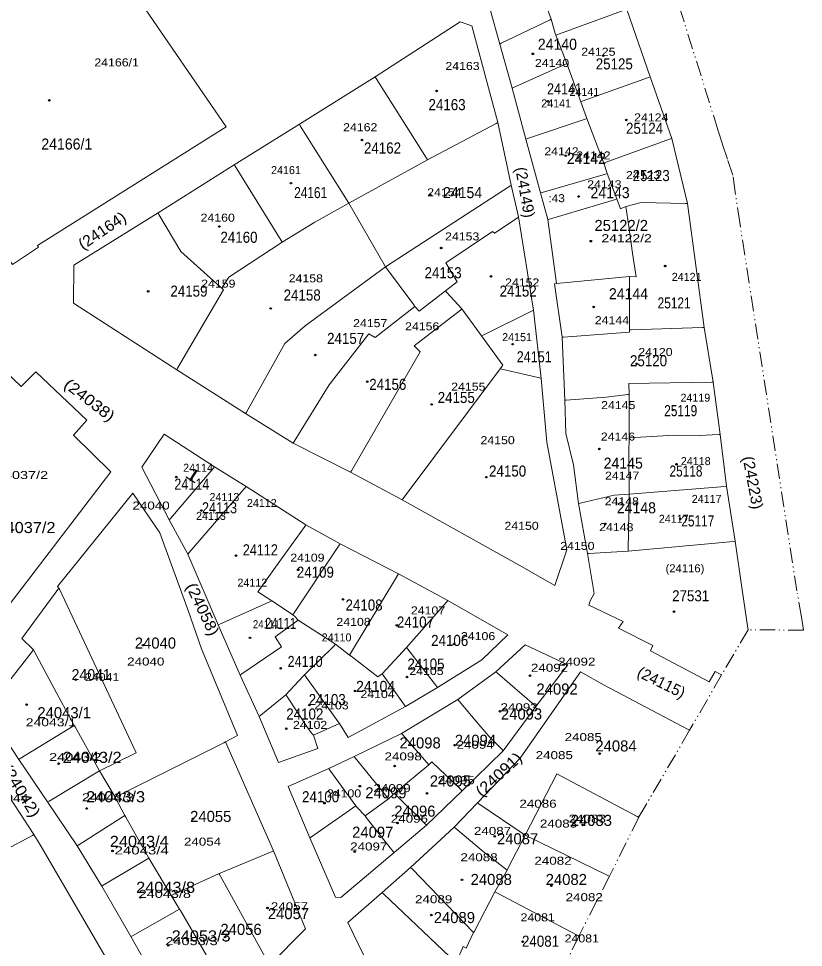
# Model space of a CAD drawing. Extents: x 649608 to 651081, y 237980 to 241202.
# Drawn here: x 650826.5 to 651081.3, y 238358.7 to 238660.5 of the extents above; entities that cross this region are included whole.
import ezdxf
from ezdxf.enums import TextEntityAlignment as Align

# ---------------------------------------------------------------- set-up
doc = ezdxf.new("R2010")
doc.units = 0
doc.header["$PDMODE"] = 32
doc.header["$PDSIZE"] = 0.5
doc.linetypes.add('DASH_DOUBLE_DOT', pattern=[9.2, 5, -1.2, 0.3, -1.2, 0.3, -1.2])
for name, color, linetype in [('19', 7, 'Continuous'), ('20', 7, 'Continuous'), ('6', 7, 'Continuous')]:
    doc.layers.add(name, color=color, linetype=linetype)
for name, color, linetype, lineweight in [('2', 7, 'DASH_DOUBLE_DOT', 13), ('3', 7, 'Continuous', 13), ('5', 7, 'Continuous', 13), ('52', 7, 'DASH_DOUBLE_DOT', 13)]:
    doc.layers.add(name, color=color, linetype=linetype, lineweight=lineweight)

msp = doc.modelspace()

# ---------------------------------------------------------------- linework, layer by layer
at = {"layer": '2'}
msp.add_line((651063.379, 238461.895), (651054.781, 238447.238), dxfattribs=at)
msp.add_lwpolyline([(651044.396, 238429.284), (651027.852, 238400.968), (651018.368, 238381.839), (651008.402, 238362.401), (650999.718, 238344.376)], dxfattribs=at)
at = {"layer": '3'}
msp.add_line((650893.931, 238625.308), (650851.505, 238687.244), dxfattribs=at)
for points in [[(650948.594, 238756.104), (650948.647, 238755.953), (650951.021, 238749.525), (650955.792, 238735.14), (650959.886, 238723.149), (650963.669, 238711.97), (650969.049, 238695.287), (650974.422, 238679.159), (650979.638, 238663.433), (650982.757, 238652.196), (650986.731, 238637.816), (650991.239, 238621.324), (650995.965, 238603.801), (650998.364, 238595.203), (651001.152, 238574.45)], [(651063.379, 238461.895), (651063.305, 238462.395), (651061.473, 238474.842), (651059.17, 238490.663), (651056.406, 238508.519), (651054.341, 238525.331), (651052.076, 238542.318), (651049.059, 238560.151), (651043.67, 238600.336), (651038.659, 238621.53), (651031.567, 238641.552), (651023.953, 238663.427), (651012.132, 238696.964), (651006.434, 238713.032), (651000.56, 238729.25)], [(650851.505, 238687.244), (650818.255, 238663.558), (650782.391, 238637.529), (650824.601, 238580.584), (650833.018, 238586.179), (650832.688, 238586.745), (650893.931, 238625.308)], [(650973.727, 238658.121), (650969.91, 238659.349), (650942.264, 238641.535), (650917.692, 238626.144), (650896.579, 238612.976), (650871.831, 238597.331)], [(650973.727, 238658.121), (650982.081, 238626.658), (650986.506, 238606.381), (650988.849, 238596.017), (650993.721, 238565.756), (650996.2, 238543.588)], [(650871.831, 238597.331), (650844.537, 238580.328), (650844.399, 238568.022), (650877.886, 238546.351), (650900.226, 238532.148), (650915.657, 238522.524), (650934.332, 238513.079), (650951.062, 238504.071)], [(651001.152, 238574.45), (651000.495, 238574.326), (651002.965, 238556.914), (651003.844, 238536.477)], [(650856.496, 238513.231), (650844.324, 238525.087), (650848.714, 238529.96), (650832.101, 238545.72), (650827.429, 238540.969), (650809.783, 238557.7), (650779.446, 238551.594)], [(650996.2, 238543.588), (650998.024, 238522.875), (651002.389, 238499.63)], [(651003.844, 238536.477), (651004.245, 238525.696), (651006.676, 238515.537), (651008.325, 238502.903), (651011.189, 238486.675)], [(650866.546, 238514.77), (650873.836, 238525.457), (650890.127, 238514.848), (650900.429, 238508.467)], [(650856.496, 238513.231), (650783.062, 238417.168), (650770.127, 238405.165)], [(650866.546, 238514.77), (650875.391, 238497.58), (650881.454, 238486.467), (650891.353, 238463.51), (650898.529, 238447.22), (650904.638, 238433.734)], [(650962.59, 238443.143), (650976.951, 238452.166), (650985.353, 238460.261), (650965.945, 238471.388), (650949.856, 238480.088), (650930.982, 238489.851), (650919.848, 238495.996), (650900.429, 238508.467)], [(650839.656, 238475.401), (650839.146, 238475.982), (650863.655, 238506.27)], [(650893.73, 238425.465), (650897.595, 238427.607), (650885.968, 238455.715), (650881.57, 238468.139), (650872.443, 238493.367), (650863.655, 238506.27)], [(650951.062, 238504.071), (650989.055, 238482.851), (651000.618, 238476.318)], [(651000.618, 238476.318), (651004.549, 238487.858), (651002.389, 238499.63)], [(651011.189, 238486.675), (651013.346, 238473.653), (651012.121, 238471.268), (651011.66, 238469.957), (651022.804, 238464.57), (651021.346, 238462.448), (651032.415, 238456.837), (651031.735, 238455.063), (651050.691, 238444.969), (651052.652, 238448.365), (651054.281, 238447.503), (651054.781, 238447.238)], [(650831.358, 238455.416), (650827.556, 238459.105), (650839.656, 238475.401)], [(651004.89, 238450.516), (650990.971, 238456.999), (650981.52, 238448.274), (650969.179, 238439.249), (650950.825, 238428.235), (650935.445, 238420.778), (650927.23, 238416.848)], [(650826.605, 238419.813), (650815.978, 238435.816), (650831.358, 238455.416)], [(650921.125, 238394.337), (650929.421, 238375.092), (650931.134, 238374.964), (650948.472, 238389.538), (650958.921, 238398.464), (650970.499, 238409.636), (650983.871, 238422.598), (650994.485, 238437.002), (651004.89, 238450.516)], [(651008.989, 238448.245), (650989.363, 238420.245), (650975.477, 238405.743), (650967.944, 238397.799), (650953.805, 238384.736), (650944.611, 238376.541)], [(651044.396, 238429.284), (651043.896, 238429.548), (651016.601, 238443.963), (651008.989, 238448.245)], [(650930.686, 238431.461), (650933.591, 238426.914), (650952.172, 238436.968), (650962.59, 238443.143)], [(650806.229, 238431.585), (650811.125, 238425.42), (650822.189, 238409.657), (650831.543, 238395.385)], [(650904.638, 238433.734), (650910.948, 238418.783), (650923.741, 238423.365), (650922.292, 238427.632), (650930.686, 238431.461)], [(650919.66, 238364.802), (650909.331, 238390.132), (650893.73, 238425.465)], [(650896.629, 238341.525), (650885.025, 238330.555), (650880.347, 238330.711), (650871.33, 238347.558), (650863.025, 238362.258), (650853.548, 238378.601), (650845.597, 238391.685), (650835.988, 238405.983), (650826.605, 238419.813)], [(650927.23, 238416.848), (650914.026, 238411.03), (650921.125, 238394.337)], [(650831.543, 238395.385), (650833.862, 238391.545), (650864.894, 238338.148)], [(650944.611, 238376.541), (650933.47, 238366.808), (650953.787, 238324.857)], [(650919.66, 238364.802), (650908.054, 238352.949), (650896.629, 238341.525)]]:
    msp.add_lwpolyline(points, dxfattribs=at)
at = {"layer": '5'}
for p, q in [((650933.706, 238600.448), (650945.648, 238579.76)), ((651001.152, 238574.45), (651024.878, 238576.658)), ((651024.886, 238558.55), (651024.886, 238559.381)), ((651001.259, 238415.17), (650990.949, 238395.151))]:
    msp.add_line(p, q, dxfattribs=at)
for points in [[(650968.909, 238740.542), (650970.097, 238737.227), (650970.888, 238737.388), (650974.373, 238727.694), (650977.245, 238720.162), (650978.452, 238717.453), (650983.561, 238704.298), (650984.021, 238702.059), (650989.061, 238688.248), (650989.987, 238685.484), (650995.652, 238670.697), (650999.401, 238660.225)], [(651000.938, 238655.114), (651023.453, 238663.246), (651023.953, 238663.427)], [(650982.757, 238652.196), (650983.257, 238652.437), (650998.901, 238659.984), (650999.401, 238660.225)], [(650999.401, 238660.225), (651000.788, 238655.614), (651000.938, 238655.114)], [(651023.679, 238599.446), (651023.179, 238599.223), (651021.948, 238598.674), (651020.779, 238601.853), (651017.617, 238610.113), (651016.522, 238613.491), (651010.995, 238627.983), (651009.029, 238633.439), (651004.574, 238645.828), (651000.938, 238655.114)], [(650986.731, 238637.816), (650987.231, 238638.041), (651004.074, 238645.603), (651004.574, 238645.828)], [(650942.264, 238641.535), (650942.579, 238641.035), (650958.934, 238615.066), (650959.249, 238614.566)], [(651009.029, 238633.439), (651009.529, 238633.619), (651031.067, 238641.372), (651031.567, 238641.552)], [(650991.239, 238621.324), (650991.739, 238621.493), (651010.495, 238627.814), (651010.995, 238627.983)], [(650917.692, 238626.144), (650918.004, 238625.644), (650933.706, 238600.448)], [(650959.249, 238614.566), (650981.581, 238626.393), (650982.081, 238626.658)], [(651016.522, 238613.491), (651017.022, 238613.673), (651038.159, 238621.348), (651038.659, 238621.53)], [(650896.579, 238612.976), (650896.888, 238612.476), (650911.797, 238588.341), (650912.106, 238587.841)], [(650912.106, 238587.841), (650922.738, 238594.306), (650933.706, 238600.448), (650959.249, 238614.566)], [(650995.965, 238603.801), (650996.465, 238603.947), (651017.117, 238609.967), (651017.617, 238610.113)], [(650945.648, 238579.76), (650986.006, 238606.055), (650986.506, 238606.381)], [(650998.364, 238595.203), (650998.864, 238595.351), (651020.279, 238601.705), (651020.779, 238601.853)], [(651023.679, 238599.446), (651028.666, 238600.738), (651043.17, 238600.349), (651043.67, 238600.336)], [(650871.831, 238597.331), (650872.126, 238596.831), (650879.229, 238584.806), (650892.001, 238573.313), (650892.501, 238572.863)], [(651024.878, 238576.658), (651027.082, 238576.554), (651025.822, 238584.235), (651024.665, 238592.892), (651023.679, 238599.446)], [(650965.157, 238572.008), (650968.88, 238574.93), (650965.282, 238581.116), (650980.445, 238591.321), (650981.091, 238590.724), (650988.349, 238595.676), (650988.849, 238596.017)], [(650892.501, 238572.863), (650894.81, 238576.474), (650912.106, 238587.841)], [(650900.226, 238532.148), (650900.505, 238532.648), (650912.946, 238554.957), (650919.549, 238560.665), (650945.648, 238579.76)], [(650945.648, 238579.76), (650954.852, 238567.439), (650955.225, 238566.939)], [(651024.886, 238559.381), (651024.878, 238576.158), (651024.878, 238576.658)], [(650877.886, 238546.351), (650878.178, 238546.851), (650893.069, 238572.341), (650892.501, 238572.863)], [(650955.225, 238566.939), (650956.571, 238565.417), (650965.157, 238572.008)], [(650965.157, 238572.008), (650965.61, 238571.508), (650970.464, 238566.146), (650976.876, 238557.423)], [(650915.657, 238522.524), (650915.965, 238523.024), (650927.359, 238541.515), (650940.277, 238558.074), (650942.335, 238556.889), (650955.225, 238566.939)], [(650934.332, 238513.079), (650934.621, 238513.579), (650956.929, 238552.178), (650955.015, 238554.121), (650969.964, 238565.757), (650970.464, 238566.146)], [(650976.876, 238557.423), (650977.376, 238557.67), (650993.221, 238565.509), (650993.721, 238565.756)], [(651002.965, 238556.914), (651003.465, 238556.951), (651024.886, 238558.55)], [(651024.886, 238559.381), (651025.386, 238559.397), (651048.559, 238560.135), (651049.059, 238560.151)], [(650976.876, 238557.423), (650983.783, 238547.847), (650982.877, 238546.65), (650951.062, 238504.071)], [(650982.877, 238546.65), (650983.377, 238546.535), (650995.7, 238543.703), (650996.2, 238543.588)], [(651024.789, 238538.39), (651024.647, 238541.967), (651051.576, 238542.312), (651052.076, 238542.318)], [(651024.789, 238538.39), (651024.289, 238538.33), (651017.348, 238537.503), (651004.344, 238536.515), (651003.844, 238536.477)], [(651024.756, 238524.309), (651024.757, 238524.809), (651024.766, 238528.536), (651024.789, 238538.39)], [(651024.756, 238524.309), (651039.462, 238525.108), (651047.477, 238525.043), (651053.841, 238525.31), (651054.341, 238525.331)], [(651024.814, 238506), (651024.695, 238519.506), (651024.756, 238524.309)], [(650890.127, 238514.848), (650889.7, 238514.348), (650875.818, 238498.08), (650875.391, 238497.58)], [(650881.454, 238486.467), (650881.885, 238486.967), (650900.429, 238508.467)], [(651024.814, 238506), (651055.906, 238508.479), (651056.406, 238508.519)], [(651008.325, 238502.903), (651008.825, 238503.02), (651019.904, 238505.608), (651024.814, 238506)], [(651024.424, 238487.408), (651024.434, 238487.908), (651024.814, 238506)], [(650908.779, 238471.344), (650904.183, 238474.277), (650912.438, 238485.704), (650919.488, 238495.496), (650919.848, 238495.996)], [(650915.57, 238466.768), (650930.648, 238489.351), (650930.982, 238489.851)], [(651024.424, 238487.408), (651058.67, 238490.616), (651059.17, 238490.663)], [(651011.189, 238486.675), (651011.689, 238486.703), (651024.424, 238487.408)], [(650949.856, 238480.088), (650949.555, 238479.588), (650933.977, 238453.698), (650929.459, 238457.186), (650917.357, 238465.075)], [(650839.656, 238475.401), (650839.89, 238474.901), (650864.731, 238421.934), (650852.856, 238416.039), (650857.901, 238407.552)], [(650891.353, 238463.51), (650891.853, 238463.735), (650908.779, 238471.344)], [(650908.779, 238471.344), (650909.279, 238471.007), (650915.57, 238466.768)], [(650952.492, 238456.128), (650965.504, 238470.888), (650965.945, 238471.388)], [(650898.529, 238447.22), (650899.029, 238447.563), (650911.919, 238456.396), (650909.855, 238459.655), (650916.857, 238464.714), (650917.357, 238465.075)], [(650917.357, 238465.075), (650916.07, 238466.294), (650915.57, 238466.768)], [(650919.315, 238447.25), (650928.959, 238456.696), (650929.459, 238457.186)], [(650933.977, 238453.698), (650934.477, 238453.314), (650943.193, 238446.621), (650944.524, 238447.654), (650952.492, 238456.128)], [(650952.492, 238456.128), (650952.881, 238455.628), (650962.201, 238443.643), (650962.59, 238443.143)], [(650831.358, 238455.416), (650831.625, 238454.916), (650838.973, 238441.17), (650844.628, 238430.84)], [(650913.319, 238440.794), (650918.851, 238446.75), (650919.315, 238447.25)], [(650930.686, 238431.461), (650930.326, 238431.961), (650919.315, 238447.25)], [(650952.172, 238436.968), (650951.814, 238437.468), (650944.882, 238447.154), (650944.524, 238447.654)], [(650994.485, 238437.002), (650993.985, 238437.437), (650982.02, 238447.839), (650981.52, 238448.274)], [(650904.638, 238433.734), (650905.138, 238434.141), (650913.319, 238440.794)], [(650913.319, 238440.794), (650913.648, 238440.294), (650920.507, 238429.856), (650921.891, 238428.132), (650922.292, 238427.632)], [(650983.871, 238422.598), (650983.382, 238423.098), (650979.202, 238427.374), (650975.3, 238431.947), (650969.598, 238438.749), (650969.179, 238439.249)], [(650844.628, 238430.84), (650827.105, 238420.119), (650826.605, 238419.813)], [(650844.628, 238430.84), (650844.906, 238430.34), (650852.856, 238416.039)], [(650857.901, 238407.552), (650893.23, 238425.215), (650893.73, 238425.465)], [(650959.727, 238418.028), (650951.261, 238427.735), (650950.825, 238428.235)], [(650935.445, 238420.778), (650935.85, 238420.278), (650946.59, 238407.034), (650939.036, 238401.438)], [(650936.026, 238404.697), (650927.592, 238416.348), (650927.23, 238416.848)], [(650948.562, 238408.724), (650949.062, 238409.141), (650959.727, 238418.028)], [(650959.727, 238418.028), (650960.21, 238418.528), (650960.726, 238419.062), (650969.999, 238410.118), (650970.499, 238409.636)], [(650835.988, 238405.983), (650836.488, 238406.281), (650852.856, 238416.039)], [(651001.259, 238415.17), (651027.352, 238401.235), (651027.852, 238400.968)], [(650857.901, 238407.552), (650858.163, 238407.052), (650861.034, 238401.566)], [(650948.562, 238408.724), (650947.09, 238407.462), (650946.59, 238407.034)], [(650958.921, 238398.464), (650958.421, 238398.959), (650948.562, 238408.724)], [(650921.125, 238394.337), (650921.625, 238394.685), (650936.026, 238404.697)], [(650939.036, 238401.438), (650936.488, 238404.197), (650936.026, 238404.697)], [(650990.949, 238395.151), (650975.977, 238405.401), (650975.477, 238405.743)], [(650861.034, 238401.566), (650846.097, 238392.005), (650845.597, 238391.685)], [(650861.034, 238401.566), (650861.316, 238401.066), (650868.88, 238387.673)], [(650939.036, 238401.438), (650939.432, 238400.938), (650948.076, 238390.038), (650948.472, 238389.538)], [(650831.543, 238395.385), (650831.043, 238395.117), (650822.125, 238390.345), (650814.267, 238385.733), (650807.944, 238381.701)], [(650967.944, 238397.799), (650968.444, 238397.378), (650977.388, 238389.838), (650985.122, 238383.847), (650981.123, 238376.78)], [(650985.122, 238383.847), (650985.38, 238384.347), (650990.949, 238395.151)], [(650990.949, 238395.151), (651017.868, 238382.082), (651018.368, 238381.839)], [(650891.47, 238382.627), (650908.831, 238389.922), (650909.331, 238390.132)], [(650868.88, 238387.673), (650854.048, 238378.897), (650853.548, 238378.601)], [(650868.88, 238387.673), (650869.177, 238387.173), (650876.065, 238375.574), (650878.792, 238371.179)], [(650974.241, 238363.562), (650954.288, 238384.236), (650953.805, 238384.736)], [(650876.065, 238375.574), (650876.565, 238375.803), (650891.47, 238382.627)], [(650891.47, 238382.627), (650891.65, 238382.678), (650907.778, 238353.449), (650908.054, 238352.949)], [(650944.611, 238376.541), (650945.111, 238376.065), (650968.571, 238353.722), (650962.028, 238341.864)], [(650981.123, 238376.78), (650974.501, 238364.062), (650974.241, 238363.562)], [(650981.123, 238376.78), (650981.623, 238376.516), (651007.902, 238362.665), (651008.402, 238362.401)], [(650878.792, 238371.179), (650863.525, 238362.541), (650863.025, 238362.258)], [(650878.792, 238371.179), (650879.082, 238370.679), (650887.429, 238356.276)], [(650968.571, 238353.722), (650968.793, 238354.222), (650970.908, 238358.996), (650971.828, 238358.515), (650974.241, 238363.562)]]:
    msp.add_lwpolyline(points, dxfattribs=at)
at = {"layer": '52'}
for p, q in [((651081.326, 238461.798), (651063.379, 238461.895)), ((651054.781, 238447.238), (651044.396, 238429.284))]:
    msp.add_line(p, q, dxfattribs=at)
msp.add_lwpolyline([(651081.326, 238461.798), (651080.759, 238465.959), (651079.219, 238474.548), (651060.64, 238594.17), (651059.155, 238604.083), (651058.44, 238609.613), (651056.636, 238614.788), (651055.058, 238619.632), (651053.581, 238624.323), (651040.863, 238664.96), (651038.983, 238669.983), (651037.177, 238674.674), (651035.497, 238679.416), (651026.689, 238704.697), (651005.715, 238762.299), (651000.638, 238776.753), (650995.266, 238791.57), (650978.475, 238836.494), (650965.122, 238871.866), (650947.956, 238918.149), (650946.31, 238922.796), (650942.749, 238932.427)], dxfattribs=at)
at = {"layer": '6'}
for p in [(650993.479, 238649.02), (651016.363, 238648.433), (650962.247, 238636.957), (650836.553, 238633.914), (650998.435, 238633.576), (651023.854, 238627.521), (650938.053, 238620.991), (651004.155, 238615.892), (651029.491, 238610.102), (650914.952, 238606.992), (650960.17, 238603.209), (651008.377, 238602.658), (650891.703, 238592.919), (651012.305, 238588.151), (650963.73, 238585.899), (651036.448, 238580.059), (650979.897, 238576.72), (650868.609, 238571.841), (650908.393, 238566.298), (651013.224, 238566.786), (650986.91, 238554.672), (650922.844, 238551.142), (651027.198, 238548.314), (650939.761, 238542.543), (650960.658, 238535.108), (651039.027, 238533.313), (651015.081, 238520.646), (651040.129, 238515.665), (650877.752, 238511.518), (650978.382, 238511.484), (650885.855, 238500.657), (651041.343, 238497.963), (651017.047, 238496.337), (650897.152, 238485.988), (650917.322, 238481.382), (650931.883, 238471.774), (651039.298, 238467.816), (650949.325, 238463.354), (650901.653, 238459.282), (650866.936, 238456.911), (650967.869, 238457.265), (650911.615, 238449.404), (650952.629, 238446.548), (650992.584, 238447), (650845.058, 238445.72), (650935.797, 238442.05), (650829.154, 238437.614), (650920.951, 238437.441), (650982.853, 238435.436), (650913.432, 238429.788), (650968.101, 238424.442), (651015.173, 238421.698), (650839.547, 238418.411), (650948.624, 238417.634), (650937.336, 238411.108), (650959.102, 238408.763), (650925.858, 238405.592), (650848.623, 238403.862), (650883.185, 238400.519), (650949.556, 238399.131), (651009.653, 238398.504), (650981.137, 238394.795), (650857.045, 238390.083), (650935.654, 238389.83), (650970.525, 238380.68), (650999.525, 238378.776), (650866.05, 238374.965), (650907.354, 238371.54), (650960.53, 238369.229), (650893.529, 238362.101), (650875.147, 238359.368), (650990.169, 238360.578)]:
    msp.add_point(p, dxfattribs=at)

# ---------------------------------------------------------------- texts
at = {"layer": '19'}
for s, width, p in [('24140', 0.95, (650995.1, 238650.326)), ('25125', 0.9, (651013.909, 238643.927)), ('24141', 0.85, (650998.093, 238635.822)), ('24163', 0.9, (650959.616, 238630.703)), ('25124', 0.9, (651023.741, 238623.023)), ('24166/1', 0.95, (650833.928, 238617.904)), ('24162', 0.9, (650938.668, 238616.625)), ('24142', 0.95, (651004.505, 238613.211)), ('25123', 0.9, (651025.88, 238607.665)), ('24161', 0.8, (650916.01, 238602.121)), ('24154', 0.95, (650964.318, 238602.121)), ('24143', 0.95, (651012.201, 238602.119)), ('24160', 0.9, (650892.068, 238587.616)), ('24153', 0.9, (650958.333, 238576.097)), ('24159', 0.9, (650875.824, 238570.125)), ('24152', 0.9, (650982.701, 238570.125)), ('24158', 0.9, (650912.589, 238568.845)), ('24144', 0.95, (651018.186, 238569.27)), ('25121', 0.8, (651034.002, 238566.284)), ('24157', 0.9, (650926.698, 238554.767)), ('24151', 0.85, (650988.258, 238548.794)), ('25120', 0.9, (651025.024, 238547.513)), ('24156', 0.9, (650940.378, 238539.835)), ('24155', 0.9, (650962.608, 238535.569)), ('25119', 0.8, (651036.14, 238531.302)), ('24145', 0.95, (651016.476, 238514.238)), ('24150', 0.9, (650979.281, 238511.679)), ('25118', 0.8, (651037.849, 238511.678)), ('24114', 0.85, (650877.105, 238507.413)), ('24113', 0.85, (650886.083, 238499.734)), ('24148', 0.95, (651020.749, 238499.733)), ('25117', 0.8, (651041.698, 238495.467)), ('24037/2', 1.1, (650819.392, 238493.334)), ('24112', 0.85, (650899.336, 238486.082)), ('24109', 0.9, (650916.863, 238478.829)), ('27531', 0.9, (651038.705, 238471.15)), ('24108', 0.9, (650932.681, 238468.164)), ('24111', 0.75, (650906.603, 238462.191)), ('24107', 0.9, (650949.354, 238462.618)), ('24106', 0.9, (650960.469, 238456.645)), ('24110', 0.85, (650913.87, 238449.819)), ('24105', 0.9, (650952.774, 238448.966)), ('24041', 0.95, (650843.76, 238445.553)), ('24104', 0.95, (650936.101, 238441.714)), ('24103', 0.9, (650920.711, 238437.448)), ('24102', 0.9, (650913.443, 238432.755)), ('24043/2', 1.1, (650840.859, 238418.686)), ('24043/3', 1.1, (650848.463, 238405.879)), ('24100', 0.9, (650918.574, 238405.879)), ('24043/4', 1.1, (650856.158, 238391.374)), ('24043/8', 1.1, (650864.708, 238376.443)), ('24053/3', 1.1, (650876.25, 238360.658)), ('24081', 0.9, (650989.968, 238358.952))]:
    msp.add_text(s, height=3.6, dxfattribs=dict(at, width=width)).set_placement(p)
for s, rotation, p in [('(24149)', 280.326, (650987.744, 238611.879)), ('(24115)', 333.478, (651027.001, 238446.946))]:
    msp.add_text(s, height=3.6, rotation=rotation, dxfattribs=at).set_placement(p)
for s, rotation, width, p in [('(24164)', 34.23, 1.05, (650847.463, 238585.208)), ('(24038)', 322.507, 1.15, (650840.912, 238540.938)), ('(24223)', 280.748, 1.05, (651061.55, 238517.936)), ('(24058)', 295.392, 1.1, (650880.766, 238476.074)), ('(24091)', 42.65, 1.1, (650976.91, 238407.43)), ('(24042)', 301.484, 1.15, (650820.818, 238416.872))]:
    msp.add_text(s, height=3.6, rotation=rotation, dxfattribs=dict(at, width=width)).set_placement(p)
for s, p in [('25122/2', (651013.482, 238591.454)), ('24040', (650864.28, 238455.792)), ('24092', (650994.67, 238440.861)), ('24043/1', (650832.645, 238433.182)), ('24093', (650983.127, 238432.756)), ('24098', (650950.209, 238423.37)), ('24094', (650968.164, 238424.223)), ('24084', (651013.792, 238422.378)), ('24095', (650960.042, 238410.999)), ('24099', (650939.095, 238407.159)), ('24096', (650948.5, 238401.187)), ('24055', (650882.235, 238399.479)), ('24083', (651005.786, 238398.2)), ('24097', (650934.819, 238394.361)), ('24087', (650981.846, 238392.227)), ('24088', (650973.296, 238379.002)), ('24082', (650997.664, 238379.002)), ('24057', (650907.458, 238367.91)), ('24089', (650961.326, 238366.63)), ('24056', (650892.068, 238362.791))]:
    msp.add_text(s, height=3.6, dxfattribs=at).set_placement(p)
at = {"layer": '20'}
for s, width, p in [('24125', 1.15, (651009.201, 238648.383)), ('24166/1', 1.15, (650851.144, 238644.919)), ('24163', 1.15, (650965.096, 238643.759)), ('24140', 1.15, (650994.163, 238644.738)), ('24124', 1.15, (651026.375, 238627.057)), ('24162', 1.15, (650931.908, 238623.87)), ('24142', 1.15, (650997.214, 238616.043)), ('24142', 1.15, (651007.601, 238614.697)), ('24123', 1.15, (651023.719, 238608.316)), ('24143', 1.15, (651011.149, 238605.333)), ('24154', 1.15, (650959.204, 238602.723)), (':43', 1.1, (650998.551, 238600.816)), ('24160', 1.15, (650885.628, 238594.495)), ('24153', 1.15, (650964.995, 238588.394)), ('24122/2', 1.3, (651015.767, 238587.808)), ('24158', 1.15, (650914.234, 238574.777)), ('24159', 1.15, (650885.836, 238573.059)), ('24152', 1.15, (650984.485, 238573.441)), ('24157', 1.15, (650935.144, 238560.218)), ('24156', 1.15, (650952.011, 238559.187)), ('24144', 1.15, (651013.616, 238561.186)), ('24120', 1.15, (651027.737, 238550.854)), ('24155', 1.15, (650966.989, 238539.584)), ('24145', 1.15, (651015.655, 238533.585)), ('24146', 1.15, (651015.575, 238523.375)), ('24150', 1.15, (650976.495, 238522.2)), ('24037/2', 1.35, (650819.179, 238510.887)), ('24147', 1.15, (651016.921, 238510.689)), ('24148', 1.15, (651016.816, 238502.352)), ('24040', 1.25, (650863.507, 238500.967)), ('24150', 1.15, (650984.267, 238494.383)), ('24148', 1.15, (651015.03, 238493.95)), ('24150', 1.15, (651002.388, 238487.862)), ('24109', 1.15, (650914.745, 238484.048)), ('(24116)', 1.05, (651036.576, 238480.578)), ('24107', 1.15, (650953.899, 238466.912)), ('24111', 0.9, (650902.609, 238462.428)), ('24108', 1.15, (650929.72, 238463.176)), ('24106', 1.15, (650970.158, 238458.554)), ('24040', 1.25, (650861.792, 238450.294)), ('24092', 1.25, (651001.717, 238450.268)), ('24105', 1.15, (650953.397, 238447.22)), ('24092', 1.25, (650992.866, 238448.274)), ('24041', 1.15, (650848.137, 238445.238)), ('24104', 1.15, (650937.512, 238439.718)), ('24103', 1.15, (650922.573, 238436.045)), ('24093', 1.25, (650982.998, 238435.445)), ('24043/1', 1.3, (650828.884, 238430.563)), ('24102', 1.15, (650915.623, 238429.714)), ('24085', 1.25, (651003.808, 238425.763)), ('24094', 1.25, (650968.741, 238423.26)), ('24085', 1.25, (650994.41, 238419.89)), ('24043/2', 1.35, (650836.455, 238419.277)), ('24098', 1.25, (650945.344, 238419.482)), ('24095', 1.25, (650962.564, 238411.744)), ('24099', 1.25, (650941.757, 238409.179)), ('24044', 1.3, (650817.175, 238405.965)), ('24043/3', 1.35, (650847.094, 238406.185)), ('24100', 1.15, (650926.637, 238407.466)), ('24086', 1.25, (650989.13, 238404.113)), ('24096', 1.25, (650947.377, 238399.242)), ('24083', 1.25, (651005.129, 238399.246)), ('24083', 1.25, (650995.786, 238397.669)), ('24087', 1.25, (650974.359, 238395.278)), ('24054', 1.25, (650880.229, 238391.79)), ('24097', 1.25, (650934.182, 238390.216)), ('24043/4', 1.4, (650857.717, 238388.94)), ('24088', 1.25, (650969.985, 238386.713)), ('24082', 1.25, (650993.999, 238385.588)), ('24043/8', 1.35, (650865.536, 238374.818)), ('24089', 1.25, (650955.247, 238373.077)), ('24082', 1.25, (651004.13, 238373.744)), ('24057', 1.25, (650908.44, 238370.787)), ('24081', 1.15, (650989.507, 238367.197)), ('24053/3', 1.35, (650874.214, 238359.468)), ('24081', 1.15, (651003.815, 238360.358))]:
    msp.add_text(s, height=2.6, dxfattribs=dict(at, width=width)).set_placement(p)
for s, p in [('24141', (651005.381, 238635.358)), ('24141', (650996.229, 238631.605)), ('24161', (650908.515, 238609.932)), ('24121', (651038.595, 238575.26)), ('24151', (650983.536, 238555.673)), ('24119', (651041.42, 238536.003)), ('24114', (650879.981, 238513.243)), ('24118', (651041.541, 238515.403)), ('24113', (650888.527, 238503.721)), ('24112', (650900.678, 238501.801)), ('24117', (651045.09, 238503.14)), ('24113', (650884.173, 238497.608)), ('24117', (651034.395, 238496.668)), ('24112', (650897.598, 238475.915)), ('24110', (650924.93, 238458.123))]:
    msp.add_text(s, height=2.6, dxfattribs=at).set_placement(p)
at = {"layer": '5', "width": 1.55}
msp.add_text('1', height=4, rotation=326.927, dxfattribs=at).set_placement((650882.112, 238510.52), align=Align.CENTER)

doc.saveas('drawing.dxf')
